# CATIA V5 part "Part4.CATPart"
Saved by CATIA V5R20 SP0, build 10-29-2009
Part number: Part4
Bounding box of the stored display mesh (mm): x -10 to 10, y -10 to 10, z -12 to 12
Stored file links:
  E:\Ehsan\Catia\Tamrin\DMU\2\Part4.CATPart
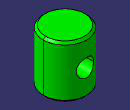
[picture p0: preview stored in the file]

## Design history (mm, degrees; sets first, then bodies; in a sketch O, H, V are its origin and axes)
Body1 (main body)
  Sketch1 on xy-plane, origin (0, 0, 0), H (1, 0, 0), V (0, 1, 0)
    circle A1 centre (0, 0) radius 10
    radius A1 = 10
  Pad1: profile Sketch1, direction (0, 0, 1), length 12, mirrored extent
  Sketch2 on zx-plane, origin (0, 0, 0), H (-1, 0, 0), V (0, 0, 1)
    circle A1 centre (0, 0) radius 4
    radius A1 = 4
  Pocket1: profile Sketch2, direction (0, -1, 0), length 12, mirrored extent
  Chamfer1: length 1, angle 45, on end face of Pad1; start face of Pad1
